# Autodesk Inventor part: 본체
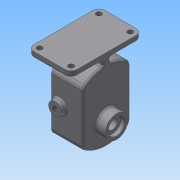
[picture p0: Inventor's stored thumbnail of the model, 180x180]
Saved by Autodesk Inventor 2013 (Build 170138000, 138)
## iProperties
Created: 2019-03
Part Number: 본체
Material: 일반
Document SubType Name: Modeling
Designer: Administrator
Density: 1 g/cm^3
Author: Administrator
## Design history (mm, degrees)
sketch "스케치1"
  geometry: L1 (-40, 44.721)-(-40, -44.721); L2 (40, 44.721)-(40, -44.721); A1 r 60 centre (0, 0) between (40, 44.721) and (-40, 44.721); A2 r 60 centre (0, 0) between (-40, -44.721) and (40, -44.721); 1 further point
  constraints: 4 end point, 4 point on circle, 2 centre point, 2 vertical, 1 coincident, 1 parallel
  dimensions: "d3" = 80 distance between parallel lines of L2 L1; "d5" = 60 radius of A1; "d6" = 60 radius of A2
extrude "돌출1" new body sketch "스케치1" distance "d7" = 53; taper "d8" = 0 deg
sketch "스케치2"
  geometry: L1 (22, 24)-(-22, 24); L2 (22, -24)-(-22, -24); A1 r 60 centre (0, 0) between (44.721, -40) and (44.721, 40) reference; A2 r 24 centre (22, 0) between (22, -24) and (22, 24); A3 r 24 centre (-22, 0) between (-22, 24) and (-22, -24); 1 further point
  constraints: 5 point on circle, 4 end point, 4 tangent, 2 centre point, 2 horizontal alignment
  dimensions: "d10" = 24 radius of A2; "d11" = 24 radius of A3; "d12" = 22 distance of A2.centre A1.centre; "d13" = 44 distance of A3.centre A2.centre
extrude "돌출2" cut sketch "스케치2" distance "d14" = 29; taper "d15" = 0 deg
sketch "스케치3"
  geometry: C1 r 12.5 at (-22, 0); C2 r 12.5 at (22, 0); A1 r 24 centre (22, 0) between (22, -24) and (22, 24) reference; A2 r 24 centre (-22, 0) between (-22, 24) and (-22, -24) reference; 1 further point
  constraints: 2 centre point, 2 coincident
  dimensions: "d16" = 12.5 radius of C1; "d18" = 12.5 radius of C2
extrude "돌출3" cut sketch "스케치3" distance "d19" = 15; taper "d20" = 0 deg
sketch "스케치4"
  geometry: C1 r 19 at (22, 0); C2 r 12.5 at (22, 0) reference
  constraints: 1 centre point, 1 concentric
  dimensions: "d21" = 19 radius of C1
extrude "돌출4" join sketch "스케치4" distance "d23" = 17; taper "d24" = 0 deg
sketch "스케치5"
  geometry: C1 r 19 at (0, 0) reference; C2 r 14 at (0, 0); 1 further point
  constraints: 1 centre point, 1 coincident
  dimensions: "d25" = 14 radius of C2
extrude "돌출5" cut sketch "스케치5" distance "d27" = 7.3; taper "d28" = 0 deg
sketch "스케치6"
  geometry: C1 r 14 at (0, 0) reference; C2 r 8.5 at (0, 0); 1 further point
  constraints: 1 centre point, 1 coincident
  dimensions: "d29" = 17 diameter of C2
extrude "돌출6" cut sketch "스케치6" stored distance "d32" = 7.3; taper "d33" = 0 deg
sketch "스케치7"
  geometry: L1 (0, 89.443)-(0, 0) reference; C1 r 11 at (14, 44.721); 2 further points
  constraints: 1 centre point, 1 horizontal alignment, 1 midpoint
  dimensions: "d34" = 11 radius of C1; "d95" = 14 distance from line of L1 C1.centre
extrude "돌출7" join sketch "스케치7" distance "d37" = 8; taper "d38" = 0 deg
sketch "스케치8"
  geometry: C1 r 11 at (0, 0) reference; 2 further points
  constraints: 1 coincident
hole "구멍1" sketch "스케치8" at (0, 0) diameter "d39" = 8.376; stored, may be unused: countersink angle "d43" = 90 deg, drill point angle "d45" = 118 deg; dims "d40" = 30, "d41" = 4, "d42" = 2, "d44" = 30
node "작업 평면1"
sketch "스케치9"
  geometry: L1 (-20, 60)-(53, 60); L2 (53, 60)-(53, -60); L3 (53, -60)-(-20, -60); L4 (-20, -60)-(-20, 60); L5 (53, -40)-(53, 40) reference; 2 further points
  constraints: 8 end point, 2 midpoint, 2 parallel, 1 horizontal, 1 perpendicular
  dimensions: "d47" = 120 distance of L3.end L1.start; "d49" = 73 distance of L1.start L1.end
extrude "돌출8" join sketch "스케치9" distance "d50" = 10; taper "d51" = 0 deg
sketch "스케치10"
  geometry: L1 (-53, 60)-(-53, -60) reference; L2 (-53, 6)-(-10, 6); L3 (-10, 6)-(-10, -6); L4 (-10, -6)-(-53, -6); L5 (-53, -6)-(-53, 6); 2 further points
  constraints: 8 end point, 2 parallel, 1 horizontal, 1 horizontal alignment, 1 midpoint, 1 perpendicular, 1 point on line
  dimensions: "d52" = 12 distance between parallel lines of L4 L2; "d55" = 43 distance of L2.start L2.end
extrude "돌출9" join sketch "스케치10" stored distance "d56" = 10; taper "d57" = 0 deg
fillet "모깎기1" dims "d58" = 10
sketch "스케치11"
  geometry: A1 r 10 centre (-43, -50) between (-53, -50) and (-43, -60) reference; A2 r 10 centre (10, -50) between (10, -60) and (20, -50) reference; A3 r 10 centre (10, 50) between (20, 50) and (10, 60) reference; A4 r 10 centre (-43, 50) between (-43, 60) and (-53, 50) reference; 1 further point
hole "구멍2" sketch "스케치11" at (-43, -50), (10, -50), (10, 50), (-43, 50) diameter "d59" = 9; stored, may be unused: countersink angle "d63" = 90 deg, drill point angle "d65" = 118 deg; dims "d60" = 30, "d61" = 4, "d62" = 2, "d64" = 30
sketch "스케치12"
  geometry: A1 r 24 centre (22, 0) between (22, -24) and (22, 24) reference; A2 r 24 centre (-22, 0) between (-22, 24) and (-22, -24) reference; 6 further points
  constraints: 4 vertical alignment, 2 horizontal alignment
  dimensions: "d66" = 31 distance of A2.centre point (-53, 0); "d67" = 31 distance of A2.centre point (-22, 31); "d68" = 31 distance of A1.centre point (22, 31); "d69" = 31 distance of A1.centre point (53, 0); "d70" = 31 distance of point (22, -31) A1.centre; "d71" = 31 distance of point (-22, -31) A2.centre
hole "구멍3" sketch "스케치12" at (-53, 0), (-22, 31), (22, 31), (53, 0), (22, -31), (-22, -31) diameter "d72" = 4.134; stored, may be unused: countersink angle "d76" = 90 deg, drill point angle "d78" = 118 deg; dims "d73" = 10, "d74" = 4, "d75" = 2, "d77" = 12
sketch "스케치13"
  geometry: L1 (-43, -60)-(10, -60) reference; L2 (20, -50)-(20, 50) reference; 2 further points
  constraints: 1 other
  dimensions: "d79" = 60 distance from line of point (10, 0) L1; "d80" = 10 distance from line of L2 point (10, 0)
feature "엠보싱1" sketch "스케치13" dims "d3" = 80, "d5" = 60, "d6" = 60, "d81" = 0.5, "d82" = 0
chamfer "모따기1" distance "d83" = 0.7; stored, may be unused: second distance "d84" = 2, angle "d85" = 30 deg
fillet "모깎기2" dims "d86" = 10
fillet "모깎기3" dims "d87" = 3
fillet "모깎기4" dims "d88" = 3
fillet "모깎기5" dims "d89" = 3
fillet "모깎기6" dims "d90" = 0.5
chamfer "모따기2" distance "d91" = 1; stored, may be unused: second distance "d92" = 2, angle "d93" = 30 deg
fillet "모깎기7" dims "d94" = 3
node "솔리드1"
mirror "대칭1"
other parameters: "d46" = 78
